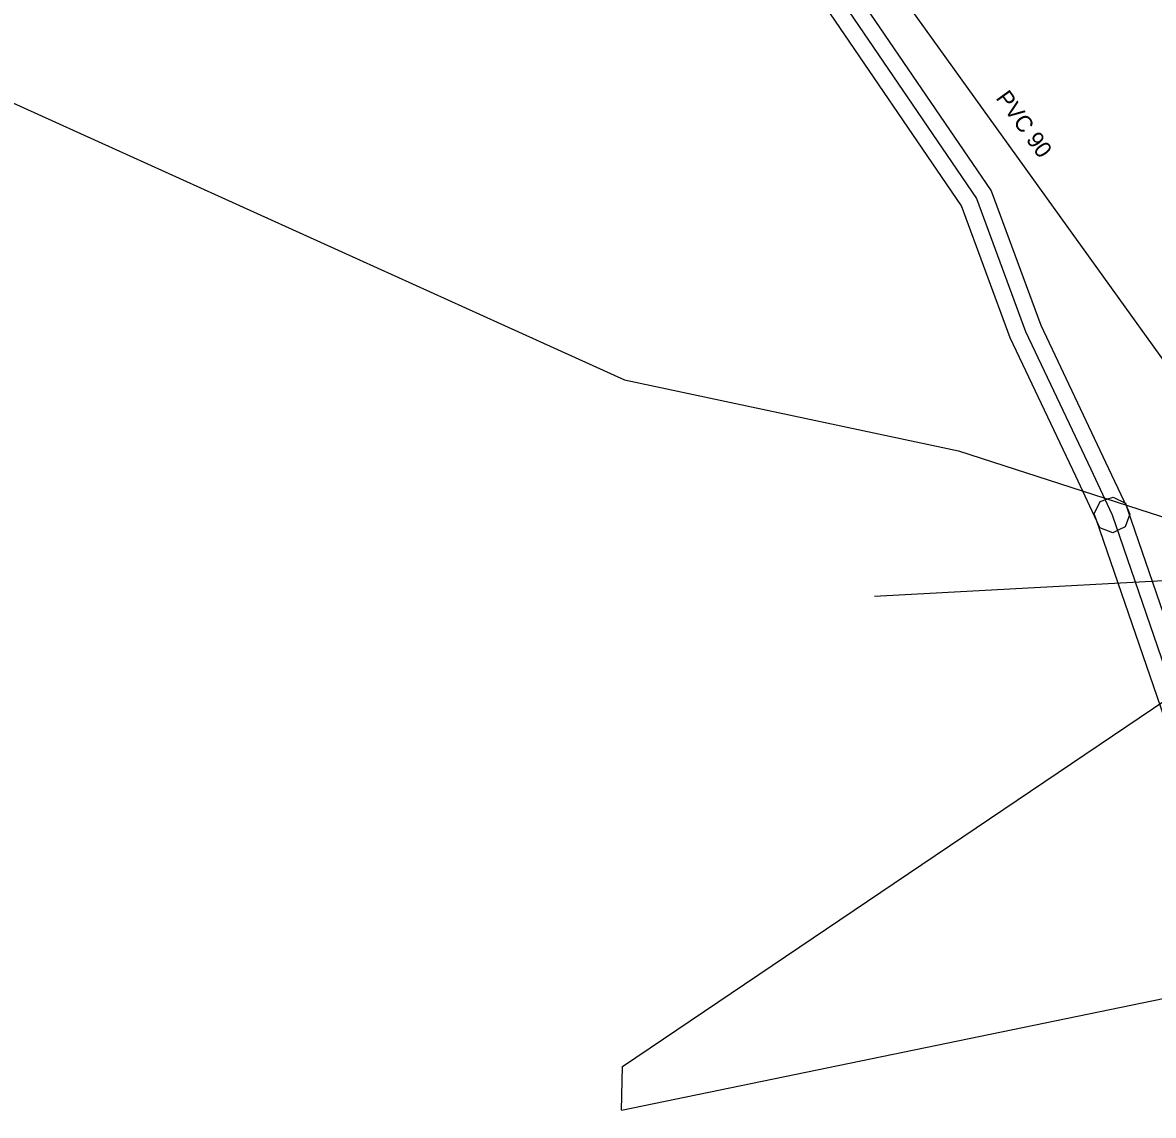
# Model space of a CAD drawing. Extents: x -743072 to -742584, y -978827 to -978325.
# Drawn here: x -742873.3 to -742804.6, y -978635.5 to -978569.2 of the extents above; entities that cross this region are included whole.
import ezdxf

# ---------------------------------------------------------------- set-up
doc = ezdxf.new("R2010")
doc.units = 0
for name, color, linetype in [('IS_GasNet_ochr pasmo', 7, 'Continuous'), ('IS_GasNet_plyn STL', 7, 'Continuous'), ('IS_popis_ScVK', 7, 'Continuous'), ('IS_ScVK_Kanal_dest', 7, 'Continuous'), ('IS_ScVK_Vodovod', 7, 'Continuous')]:
    doc.layers.add(name, color=color, linetype=linetype)

msp = doc.modelspace()

# ---------------------------------------------------------------- linework, layer by layer
at = {"layer": 'IS_GasNet_ochr pasmo'}
msp.add_lwpolyline([(-742823.148, -978566.61), (-742814.434, -978579.399), (-742811.427, -978587.562), (-742807.486, -978595.883), (-742806.2, -978598.622), (-742806.181, -978598.662), (-742806.008, -978599.039), (-742806.296, -978599.816), (-742806.672, -978599.989), (-742807.049, -978600.162), (-742807.826, -978599.874), (-742807.999, -978599.498), (-742808.014, -978599.464), (-742809.294, -978596.737), (-742813.273, -978588.338), (-742816.226, -978580.321), (-742824.792, -978567.75)], dxfattribs=at)
msp.add_lwpolyline([(-742798.985, -978621.533), (-742801.529, -978619.869), (-742803.905, -978611.408), (-742808.036, -978599.405), (-742808.171, -978599.014), (-742807.807, -978598.269), (-742807.415, -978598.134), (-742807.024, -978597.999), (-742806.279, -978598.363), (-742806.144, -978598.755), (-742801.995, -978610.812)], close=True, dxfattribs=at)
at = {"layer": 'IS_GasNet_plyn STL'}
for points in [[(-742871.432, -978510.314), (-742866.77, -978515.61), (-742859.158, -978524.614), (-742856, -978528.35), (-742849.97, -978535.17), (-742848.85, -978536.31), (-742844.679, -978540.783), (-742839.05, -978546.82), (-742835.63, -978550.66), (-742823.97, -978567.18), (-742815.33, -978579.86), (-742812.35, -978587.95), (-742808.39, -978596.31), (-742807.107, -978599.043), (-742807.09, -978599.08)], [(-742807.09, -978599.08), (-742802.95, -978611.11), (-742800.257, -978620.701)]]:
    msp.add_lwpolyline(points, dxfattribs=at)
at = {"layer": 'IS_ScVK_Kanal_dest'}
for points in [[(-742836.89, -978635.23), (-742836.829, -978632.584), (-742794.674, -978604.136), (-742784.548, -978596.4), (-742778.303, -978601.806), (-742769.218, -978607.658), (-742757.236, -978613.629), (-742748.697, -978616.71), (-742737.016, -978619.72), (-742706.897, -978621.455), (-742694.704, -978621.477), (-742669.125, -978621.524), (-742647.601, -978624.622), (-742643.224, -978625.196), (-742627.191, -978628.893), (-742614.992, -978632.031), (-742608.58, -978633.224), (-742593.026, -978634.809), (-742583.863, -978635.543)], [(-742796.109, -978602.67), (-742821.52, -978604.039)], [(-742836.89, -978635.23), (-742774.92, -978622.46)]]:
    msp.add_lwpolyline(points, dxfattribs=at)
at = {"layer": 'IS_ScVK_Vodovod'}
for points in [[(-742799.35, -978596.101), (-742827.12, -978557.465), (-742850.787, -978530.098)], [(-742915.09, -978596.84), (-742888.226, -978574.263), (-742883.014, -978569.821), (-742878.561, -978571.932), (-742836.693, -978590.888), (-742816.409, -978595.182), (-742800.716, -978600.266)]]:
    msp.add_lwpolyline(points, dxfattribs=at)

# ---------------------------------------------------------------- texts
at = {"layer": 'IS_popis_ScVK'}
msp.add_text('PVC 90', height=1, rotation=306, dxfattribs=at).set_placement((-742814.185, -978573.771))

doc.saveas('drawing.dxf')
